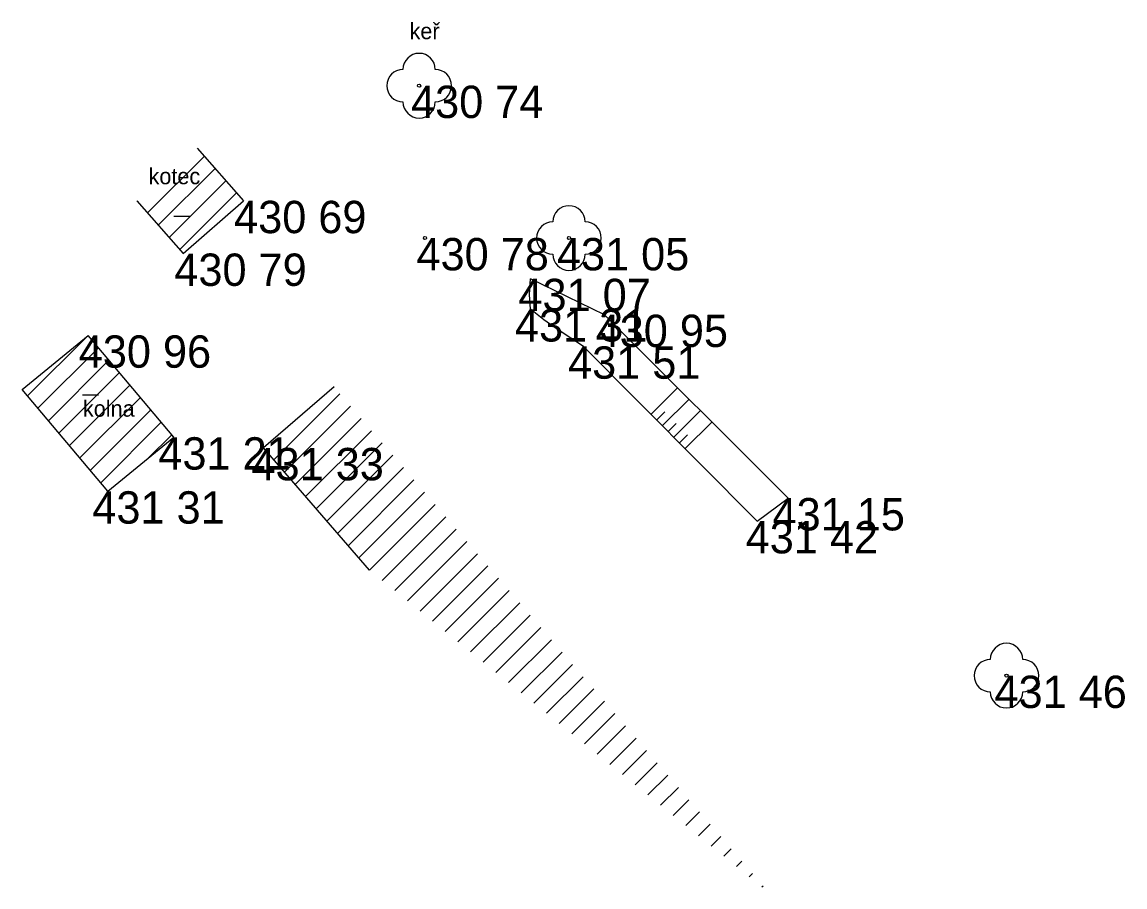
# Model space of a CAD drawing. Extents: x -554123 to -553118, y -1076825 to -1073672.
# Drawn here: x -554123.05 to -554088.97, y -1073921.55 to -1073894.81 of the extents above; entities that cross this region are included whole.
import ezdxf

# ---------------------------------------------------------------- set-up
doc = ezdxf.new("R2010")
doc.units = 0
for name, color, linetype in [('1', 7, 'Continuous'), ('14', 7, 'Continuous'), ('26', 7, 'Continuous'), ('27', 7, 'Continuous'), ('32', 7, 'Continuous'), ('34', 7, 'Continuous'), ('47', 7, 'Continuous'), ('52', 7, 'Continuous'), ('6', 7, 'Continuous')]:
    doc.layers.add(name, color=color, linetype=linetype)

# ---------------------------------------------------------------- blocks, each defined once
blk = doc.blocks.new('POINT_DISPLAY')
blk.add_line((0, 0), (0, 0))
blk = doc.blocks.new('STL')
at = {"layer": '34'}
blk.add_circle((0, 0), 0.05, dxfattribs=at)
for centre, start, end in [((0, 0.5), 0, 180), ((-0.5, 0), 90, 270), ((0.5, 0), 270, 90), ((0, -0.5), 180, 0)]:
    blk.add_arc(centre, 0.5, start, end, dxfattribs=at)
blk = doc.blocks.new('T')
at = {"layer": '6'}
blk.add_circle((0, 0), 0.05, dxfattribs=at)
blk = doc.blocks.new('KER')
at = {"layer": '34'}
blk.add_circle((0, 0), 0.05, dxfattribs=at)
for centre, start, end in [((0, 0.5), 0, 180), ((-0.5, 0), 90, 270), ((0.5, 0), 270, 90), ((0, -0.5), 180, 0)]:
    blk.add_arc(centre, 0.5, start, end, dxfattribs=at)
blk = doc.blocks.new('BN')
at = {"layer": '47'}
blk.add_line((-0.25, 0), (0.25, 0), dxfattribs=at)

msp = doc.modelspace()

# ---------------------------------------------------------------- linework, layer by layer
at = {"layer": '14'}
for p, q in [((-554117.639, -1073898.709), (-554116.21, -1073900.34)), ((-554119.499, -1073900.339), (-554118.07, -1073901.97)), ((-554118.07, -1073901.97), (-554116.21, -1073900.34)), ((-554123.05, -1073906.17), (-554121.01, -1073904.5)), ((-554118.36, -1073907.65), (-554121.01, -1073904.5)), ((-554120.4, -1073909.32), (-554123.05, -1073906.17)), ((-554113.41, -1073906.093), (-554115.59, -1073907.98)), ((-554120.4, -1073909.32), (-554118.36, -1073907.65)), ((-554112.318, -1073911.76), (-554115.59, -1073907.98))]:
    msp.add_line(p, q, dxfattribs=at)
at = {"layer": '26'}
for p, q in [((-554103.615, -1073906.937), (-554102.792, -1073906.118)), ((-554103.262, -1073907.291), (-554102.438, -1073906.472)), ((-554103.439, -1073907.114), (-554103.191, -1073906.868)), ((-554102.91, -1073907.646), (-554102.085, -1073906.825)), ((-554103.086, -1073907.469), (-554102.838, -1073907.223)), ((-554102.557, -1073908), (-554101.731, -1073907.179)), ((-554102.733, -1073907.823), (-554102.486, -1073907.577))]:
    msp.add_line(p, q, dxfattribs=at)
at = {"layer": '27'}
for p, q in [((-554105.05, -1073903.86), (-554107.34, -1073902.75)), ((-554099.38, -1073909.53), (-554105.05, -1073903.86)), ((-554100.33, -1073910.24), (-554105.7, -1073904.84)), ((-554100.33, -1073910.24), (-554099.38, -1073909.53))]:
    msp.add_line(p, q, dxfattribs=at)
for points in [[(-554107.34, -1073903.69), (-554107.366, -1073903.241), (-554107.34, -1073902.75)], [(-554105.7, -1073904.84), (-554106.484, -1073904.333), (-554106.928, -1073904.018), (-554107.34, -1073903.69)]]:
    msp.add_lwpolyline(points, dxfattribs=at)
at = {"layer": '32'}
for p, q in [((-554119.169, -1073900.716), (-554117.416, -1073898.963)), ((-554118.839, -1073901.093), (-554117.086, -1073899.34)), ((-554118.508, -1073901.47), (-554116.756, -1073899.717)), ((-554118.178, -1073901.847), (-554116.426, -1073900.094)), ((-554122.881, -1073906.371), (-554121.01, -1073904.5)), ((-554122.558, -1073906.755), (-554120.687, -1073904.884)), ((-554122.235, -1073907.139), (-554120.364, -1073905.268)), ((-554121.912, -1073907.523), (-554120.041, -1073905.652)), ((-554121.589, -1073907.907), (-554119.718, -1073906.036)), ((-554121.266, -1073908.291), (-554119.395, -1073906.42)), ((-554115.271, -1073908.349), (-554113.227, -1073906.305)), ((-554120.942, -1073908.675), (-554119.072, -1073906.804)), ((-554114.943, -1073908.728), (-554112.901, -1073906.686)), ((-554120.619, -1073909.059), (-554118.748, -1073907.188)), ((-554114.615, -1073909.107), (-554112.574, -1073907.066)), ((-554119.149, -1073908.296), (-554118.425, -1073907.572)), ((-554114.287, -1073909.486), (-554112.247, -1073907.446)), ((-554113.958, -1073909.865), (-554111.92, -1073907.827)), ((-554113.63, -1073910.244), (-554111.593, -1073908.207)), ((-554113.302, -1073910.623), (-554111.266, -1073908.587)), ((-554112.974, -1073911.002), (-554110.94, -1073908.967)), ((-554112.646, -1073911.381), (-554110.613, -1073909.348)), ((-554112.318, -1073911.76), (-554110.286, -1073909.728)), ((-554111.927, -1073912.076), (-554109.959, -1073910.108)), ((-554111.536, -1073912.392), (-554109.632, -1073910.489)), ((-554111.144, -1073912.708), (-554109.306, -1073910.869)), ((-554110.753, -1073913.024), (-554108.979, -1073911.249)), ((-554110.362, -1073913.339), (-554108.652, -1073911.629)), ((-554109.971, -1073913.655), (-554108.325, -1073912.01)), ((-554109.58, -1073913.971), (-554107.998, -1073912.39)), ((-554109.188, -1073914.287), (-554107.671, -1073912.77)), ((-554108.797, -1073914.603), (-554107.345, -1073913.151)), ((-554108.406, -1073914.919), (-554107.018, -1073913.531)), ((-554108.015, -1073915.235), (-554106.691, -1073913.911)), ((-554107.623, -1073915.551), (-554106.364, -1073914.291)), ((-554107.232, -1073915.867), (-554106.037, -1073914.672)), ((-554106.841, -1073916.182), (-554105.71, -1073915.052)), ((-554106.45, -1073916.498), (-554105.384, -1073915.432)), ((-554106.059, -1073916.814), (-554105.057, -1073915.813)), ((-554105.667, -1073917.13), (-554104.73, -1073916.193)), ((-554105.276, -1073917.446), (-554104.403, -1073916.573)), ((-554104.885, -1073917.762), (-554104.076, -1073916.953)), ((-554104.494, -1073918.078), (-554103.749, -1073917.334)), ((-554104.103, -1073918.394), (-554103.423, -1073917.714)), ((-554103.711, -1073918.71), (-554103.096, -1073918.094)), ((-554103.32, -1073919.026), (-554102.769, -1073918.474)), ((-554102.929, -1073919.341), (-554102.442, -1073918.855)), ((-554102.538, -1073919.657), (-554102.115, -1073919.235)), ((-554102.146, -1073919.973), (-554101.789, -1073919.615)), ((-554101.755, -1073920.289), (-554101.462, -1073919.996)), ((-554101.364, -1073920.605), (-554101.135, -1073920.376)), ((-554100.973, -1073920.921), (-554100.808, -1073920.756)), ((-554100.582, -1073921.237), (-554100.481, -1073921.136)), ((-554100.19, -1073921.553), (-554100.154, -1073921.517))]:
    msp.add_line(p, q, dxfattribs=at)

# ---------------------------------------------------------------- block references
at = {"layer": '1'}
for p in [(-554110.78, -1073896.78), (-554116.21, -1073900.34), (-554110.6, -1073901.49), (-554106.15, -1073901.49), (-554118.07, -1073901.97), (-554109.52, -1073902.74), (-554107.34, -1073902.75), (-554107.34, -1073903.69), (-554105.05, -1073903.86), (-554121.01, -1073904.5), (-554105.7, -1073904.84), (-554118.36, -1073907.65), (-554115.59, -1073907.98), (-554120.4, -1073909.32), (-554099.38, -1073909.53), (-554100.33, -1073910.24), (-554092.63, -1073915.02)]:
    msp.add_blockref('POINT_DISPLAY', p, dxfattribs=at)
at = {"layer": '32'}
for p in [(-554119.499, -1073900.339), (-554121.01, -1073904.5), (-554112.318, -1073911.76)]:
    msp.add_blockref('POINT_DISPLAY', p, dxfattribs=at)
at = {"layer": '34'}
for name, p in [('KER', (-554110.78, -1073896.78)), ('STL', (-554106.15, -1073901.49)), ('STL', (-554092.63, -1073915.02))]:
    msp.add_blockref(name, p, dxfattribs=at)
at = {"layer": '47'}
for p in [(-554118.109, -1073900.814), (-554120.936, -1073906.343)]:
    msp.add_blockref('BN', p, dxfattribs=at)
at = {"layer": '6'}
msp.add_blockref('T', (-554110.6, -1073901.49), dxfattribs=at)

# ---------------------------------------------------------------- texts
at = {"layer": '52'}
for s, p in [('keř', (-554111.077, -1073895.342)), ('kotec', (-554119.142, -1073899.828)), ('kolna', (-554121.17, -1073907.014))]:
    msp.add_text(s, height=0.5, dxfattribs=at).set_placement(p)
at = {"layer": '6'}
for s, p in [('430 74 ', (-554111.03, -1073897.78)), ('430 69 ', (-554116.498, -1073901.34)), ('430 78 ', (-554110.862, -1073902.49)), ('431 05 ', (-554106.523, -1073902.49)), ('430 79 ', (-554118.344, -1073902.97)), ('431 07 ', (-554107.711, -1073903.75)), ('431 31 ', (-554107.818, -1073904.69)), ('430 95 ', (-554105.326, -1073904.86)), ('430 96 ', (-554121.298, -1073905.5)), ('431 51 ', (-554106.178, -1073905.84)), ('431 21 ', (-554118.838, -1073908.65)), ('431 33 ', (-554115.961, -1073908.98)), ('431 31 ', (-554120.878, -1073910.32)), ('431 15 ', (-554099.86, -1073910.53)), ('431 42 ', (-554100.689, -1073911.24)), ('431 46 ', (-554093.001, -1073916.02))]:
    msp.add_text(s, height=1, dxfattribs=at).set_placement(p)

doc.saveas('drawing.dxf')
